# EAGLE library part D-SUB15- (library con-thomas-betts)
D-Subminiatur Connector Source: Electronioc Interconnects European Edition 1998
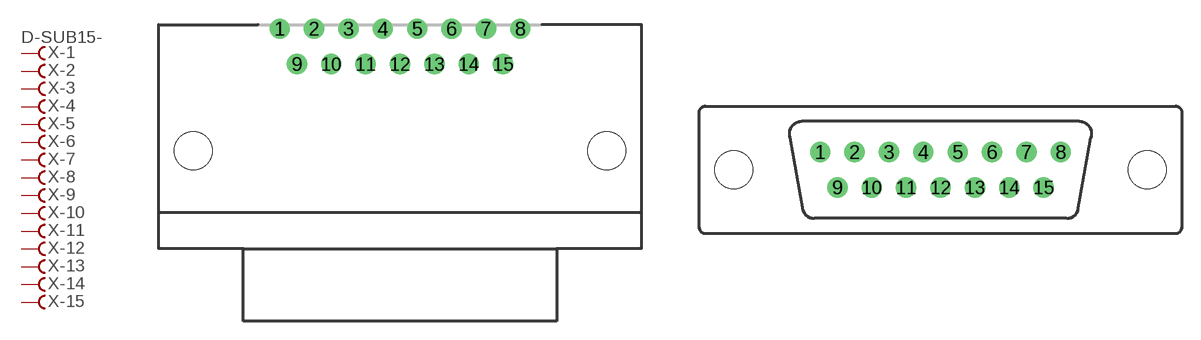
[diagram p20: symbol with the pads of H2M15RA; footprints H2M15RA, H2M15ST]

Designator prefix X; gates -1=FV -2=F -3=F -4=F -5=F -6=F -7=F -8=F -9=F -10=F -11=F -12=F -13=F -14=F -15=F

## D-SUB15-H2M15RA (MPN: H2M15RA29B; OC_FARNELL: unknown; OC_NEWARK: 93F8395)  [H2M15RA]
1  -1:F  pas
2  -2:F  pas
3  -3:F  pas
4  -4:F  pas
5  -5:F  pas
6  -6:F  pas
7  -7:F  pas
8  -8:F  pas
9  -9:F  pas
10  -10:F  pas
11  -11:F  pas
12  -12:F  pas
13  -13:F  pas
14  -14:F  pas
15  -15:F  pas

## D-SUB15-H2M15ST (OC_FARNELL: unknown; OC_NEWARK: unknown)  [H2M15ST]
Pads as for H2M15RA

## D-SUB15-H2R15RA (OC_FARNELL: unknown; OC_NEWARK: unknown)  [H2R15RA]
Pads as for H2M15RA

## D-SUB15-H2R15ST (OC_FARNELL: unknown; OC_NEWARK: unknown)  [H2R15ST]
Pads as for H2M15RA

## D-SUB15-H3M15RA (OC_FARNELL: unknown; OC_NEWARK: unknown)  [H3M15RA]
Pads as for H2M15RA

## D-SUB15-H5M15RA (MF: TYCO ELECTRONICS; MPN: H5M15RA29C; OC_FARNELL: unknown; OC_NEWARK: 93F8315)  [H5M15RA]
Pads as for H2M15RA

## D-SUB15-H5R15RA (MF: TYCO ELECTRONICS; MPN: H5R15RA29B; OC_FARNELL: unknown; OC_NEWARK: 93F8335)  [H5R15RA]
Pads as for H2M15RA

## D-SUB15-HDR15RA (OC_FARNELL: unknown; OC_NEWARK: unknown)  [HDR15RA]
Pads as for H2M15RA

## Footprint H2M15RA (pad centres in mm)
THOMAS&BETTS H2M15RA29A
drill 1.092 round: 1 -9.69,7.925; 2 -6.921,7.925; 3 -4.153,7.925; 4 -1.384,7.925; 5 1.384,7.925; 6 4.153,7.925; 7 6.921,7.925; 8 9.69,7.925; 9 -8.306,5.08; 10 -5.537,5.08; 11 -2.769,5.08; 12 0,5.08; 13 2.769,5.08; 14 5.537,5.08; 15 8.306,5.08
hole 3.048 at -16.662,-1.905
hole 3.048 at 16.662,-1.905

## Footprint H2M15ST (pad centres in mm)
THOMAS&BETTS H2M15ST29x
drill 1.092 round: 1 -9.69,1.422; 2 -6.921,1.422; 3 -4.153,1.422; 4 -1.384,1.422; 5 1.384,1.422; 6 4.153,1.422; 7 6.921,1.422; 8 9.69,1.422; 9 -8.306,-1.422; 10 -5.537,-1.422; 11 -2.769,-1.422; 12 0,-1.422; 13 2.769,-1.422; 14 5.537,-1.422; 15 8.306,-1.422
hole 3.048 at -16.662,0
hole 3.048 at 16.662,0

## Footprint H2R15RA (pad centres in mm)
THOMAS&BETTS H2R15RA29A
drill 1.092 round: 1 9.69,7.925; 2 6.921,7.925; 3 4.153,7.925; 4 1.384,7.925; 5 -1.384,7.925; 6 -4.153,7.925; 7 -6.921,7.925; 8 -9.69,7.925; 9 8.306,5.08; 10 5.537,5.08; 11 2.769,5.08; 12 0,5.08; 13 -2.769,5.08; 14 -5.537,5.08; 15 -8.306,5.08
hole 3.048 at -16.662,-1.905
hole 3.048 at 16.662,-1.905

## Footprint H2R15ST (pad centres in mm)
THOMAS&BETTS H2R15ST29x
drill 1.092 round: 1 9.69,1.422; 2 6.921,1.422; 3 4.153,1.422; 4 1.384,1.422; 5 -1.384,1.422; 6 -4.153,1.422; 7 -6.921,1.422; 8 -9.69,1.422; 9 8.306,-1.422; 10 5.537,-1.422; 11 2.769,-1.422; 12 0,-1.422; 13 -2.769,-1.422; 14 -5.537,-1.422; 15 -8.306,-1.422
hole 3.048 at -16.662,0
hole 3.048 at 16.662,0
